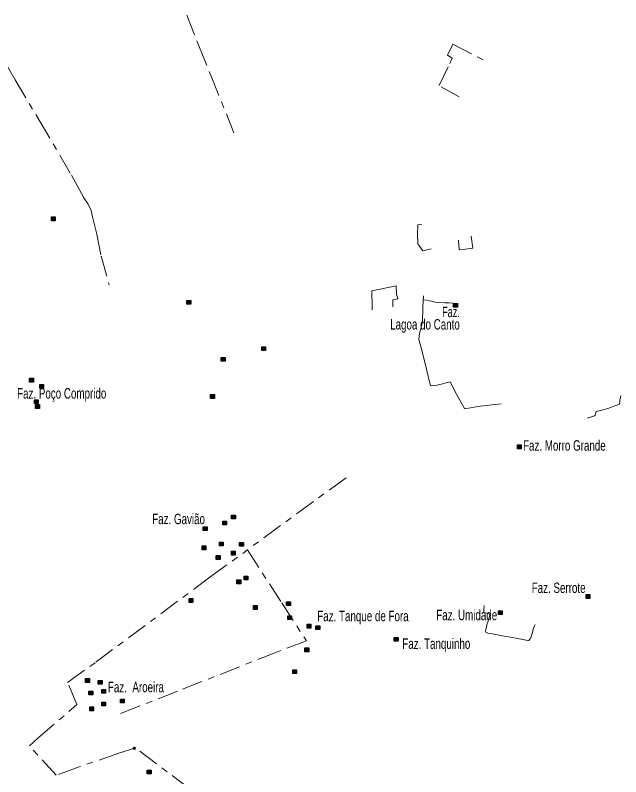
# Model space of a CAD drawing. Extents: x 445.4 to 500, y 8728.7 to 8784.
# Drawn here: x 450.41 to 459.68, y 8772.32 to 8783.97 of the extents above; entities that cross this region are included whole.
import ezdxf
from ezdxf.enums import TextEntityAlignment as Align

# ---------------------------------------------------------------- set-up
doc = ezdxf.new("R2010")
doc.units = 0
doc.header["$LTSCALE"] = 0.064
doc.header["$PDMODE"] = 32
doc.header["$PDSIZE"] = 0.032
doc.linetypes.add('DOT_DASHED', pattern=[7.7, 5, -1.2, 0.3, -1.2])
doc.layers.add('2', color=7, linetype='Continuous', lineweight=25)
doc.layers.add('22', color=7, linetype='DOT_DASHED', lineweight=13)
doc.layers.add('61', color=7, linetype='Continuous')

msp = doc.modelspace()

# ---------------------------------------------------------------- hatches: boundary and pattern name
at = {"layer": '2'}
for points in [[(450.9666, 8780.8868), (451.0246, 8780.8868), (451.0246, 8780.8288), (450.9666, 8780.8288)], [(453.0401, 8779.6071), (453.0981, 8779.6071), (453.0981, 8779.5491), (453.0401, 8779.5491)], [(457.1206, 8779.562), (457.1786, 8779.562), (457.1786, 8779.504), (457.1206, 8779.504)], [(454.1849, 8778.9008), (454.2429, 8778.9008), (454.2429, 8778.8428), (454.1849, 8778.8428)], [(453.565, 8778.7378), (453.623, 8778.7378), (453.623, 8778.6798), (453.565, 8778.6798)], [(450.6312, 8778.4171), (450.6892, 8778.4171), (450.6892, 8778.3591), (450.6312, 8778.3591)], [(450.7885, 8778.3217), (450.8465, 8778.3217), (450.8465, 8778.2637), (450.7885, 8778.2637)], [(450.7066, 8778.0871), (450.7646, 8778.0871), (450.7646, 8778.0291), (450.7066, 8778.0291)], [(453.4021, 8778.1673), (453.4601, 8778.1673), (453.4601, 8778.1093), (453.4021, 8778.1093)], [(450.7223, 8778.0151), (450.7803, 8778.0151), (450.7803, 8777.9571), (450.7223, 8777.9571)], [(458.0989, 8777.398), (458.1569, 8777.398), (458.1569, 8777.34), (458.0989, 8777.34)], [(453.7233, 8776.3229), (453.7813, 8776.3229), (453.7813, 8776.2649), (453.7233, 8776.2649)], [(453.5876, 8776.2324), (453.6456, 8776.2324), (453.6456, 8776.1744), (453.5876, 8776.1744)], [(453.289, 8776.1464), (453.347, 8776.1464), (453.347, 8776.0884), (453.289, 8776.0884)], [(453.2709, 8775.8521), (453.3289, 8775.8521), (453.3289, 8775.7941), (453.2709, 8775.7941)], [(453.5378, 8775.9109), (453.5958, 8775.9109), (453.5958, 8775.8529), (453.5378, 8775.8529)], [(453.8455, 8775.9064), (453.9035, 8775.9064), (453.9035, 8775.8484), (453.8455, 8775.8484)], [(453.7188, 8775.7706), (453.7768, 8775.7706), (453.7768, 8775.7126), (453.7188, 8775.7126)], [(453.4881, 8775.7027), (453.5461, 8775.7027), (453.5461, 8775.6447), (453.4881, 8775.6447)], [(453.9134, 8775.3903), (453.9714, 8775.3903), (453.9714, 8775.3323), (453.9134, 8775.3323)], [(453.8048, 8775.3314), (453.8628, 8775.3314), (453.8628, 8775.2734), (453.8048, 8775.2734)], [(453.0718, 8775.0462), (453.1298, 8775.0462), (453.1298, 8774.9882), (453.0718, 8774.9882)], [(459.1485, 8775.1073), (459.2065, 8775.1073), (459.2065, 8775.0493), (459.1485, 8775.0493)], [(454.058, 8774.9387), (454.116, 8774.9387), (454.116, 8774.8807), (454.058, 8774.8807)], [(454.5649, 8774.9964), (454.6229, 8774.9964), (454.6229, 8774.9384), (454.5649, 8774.9384)], [(457.8068, 8774.8599), (457.8648, 8774.8599), (457.8648, 8774.8019), (457.8068, 8774.8019)], [(454.5823, 8774.7825), (454.6403, 8774.7825), (454.6403, 8774.7245), (454.5823, 8774.7245)], [(454.8772, 8774.6523), (454.9352, 8774.6523), (454.9352, 8774.5943), (454.8772, 8774.5943)], [(455.0129, 8774.6297), (455.0709, 8774.6297), (455.0709, 8774.5717), (455.0129, 8774.5717)], [(456.212, 8774.4507), (456.27, 8774.4507), (456.27, 8774.3927), (456.212, 8774.3927)], [(454.8455, 8774.2901), (454.9035, 8774.2901), (454.9035, 8774.2321), (454.8455, 8774.2321)], [(454.66, 8773.9551), (454.718, 8773.9551), (454.718, 8773.8971), (454.66, 8773.8971)], [(451.4884, 8773.8216), (451.5464, 8773.8216), (451.5464, 8773.7636), (451.4884, 8773.7636)], [(451.6831, 8773.7926), (451.7411, 8773.7926), (451.7411, 8773.7346), (451.6831, 8773.7346)], [(451.7369, 8773.6558), (451.7949, 8773.6558), (451.7949, 8773.5978), (451.7369, 8773.5978)], [(451.5395, 8773.6303), (451.5975, 8773.6303), (451.5975, 8773.5723), (451.5395, 8773.5723)], [(451.7369, 8773.4611), (451.7949, 8773.4611), (451.7949, 8773.4031), (451.7369, 8773.4031)], [(452.0226, 8773.5066), (452.0806, 8773.5066), (452.0806, 8773.4486), (452.0226, 8773.4486)], [(451.5516, 8773.3882), (451.6096, 8773.3882), (451.6096, 8773.3302), (451.5516, 8773.3302)], [(452.4326, 8772.421), (452.4906, 8772.421), (452.4906, 8772.363), (452.4326, 8772.363)]]:
    msp.add_hatch(color=256, dxfattribs=at).paths.add_polyline_path(points)

# ---------------------------------------------------------------- linework, layer by layer
for points in [[(450.9666, 8780.8868), (451.0246, 8780.8868), (451.0246, 8780.8288), (450.9666, 8780.8288)], [(453.0401, 8779.6071), (453.0981, 8779.6071), (453.0981, 8779.5491), (453.0401, 8779.5491)], [(457.1206, 8779.562), (457.1786, 8779.562), (457.1786, 8779.504), (457.1206, 8779.504)], [(454.1849, 8778.9008), (454.2429, 8778.9008), (454.2429, 8778.8428), (454.1849, 8778.8428)], [(453.565, 8778.7378), (453.623, 8778.7378), (453.623, 8778.6798), (453.565, 8778.6798)], [(450.6312, 8778.4171), (450.6892, 8778.4171), (450.6892, 8778.3591), (450.6312, 8778.3591)], [(450.7885, 8778.3217), (450.8465, 8778.3217), (450.8465, 8778.2637), (450.7885, 8778.2637)], [(450.7066, 8778.0871), (450.7646, 8778.0871), (450.7646, 8778.0291), (450.7066, 8778.0291)], [(453.4021, 8778.1673), (453.4601, 8778.1673), (453.4601, 8778.1093), (453.4021, 8778.1093)], [(450.7223, 8778.0151), (450.7803, 8778.0151), (450.7803, 8777.9571), (450.7223, 8777.9571)], [(458.0989, 8777.398), (458.1569, 8777.398), (458.1569, 8777.34), (458.0989, 8777.34)], [(453.7233, 8776.3229), (453.7813, 8776.3229), (453.7813, 8776.2649), (453.7233, 8776.2649)], [(453.5876, 8776.2324), (453.6456, 8776.2324), (453.6456, 8776.1744), (453.5876, 8776.1744)], [(453.289, 8776.1464), (453.347, 8776.1464), (453.347, 8776.0884), (453.289, 8776.0884)], [(453.2709, 8775.8521), (453.3289, 8775.8521), (453.3289, 8775.7941), (453.2709, 8775.7941)], [(453.5378, 8775.9109), (453.5958, 8775.9109), (453.5958, 8775.8529), (453.5378, 8775.8529)], [(453.8455, 8775.9064), (453.9035, 8775.9064), (453.9035, 8775.8484), (453.8455, 8775.8484)], [(453.7188, 8775.7706), (453.7768, 8775.7706), (453.7768, 8775.7126), (453.7188, 8775.7126)], [(453.4881, 8775.7027), (453.5461, 8775.7027), (453.5461, 8775.6447), (453.4881, 8775.6447)], [(453.9134, 8775.3903), (453.9714, 8775.3903), (453.9714, 8775.3323), (453.9134, 8775.3323)], [(453.8048, 8775.3314), (453.8628, 8775.3314), (453.8628, 8775.2734), (453.8048, 8775.2734)], [(453.0718, 8775.0462), (453.1298, 8775.0462), (453.1298, 8774.9882), (453.0718, 8774.9882)], [(459.1485, 8775.1073), (459.2065, 8775.1073), (459.2065, 8775.0493), (459.1485, 8775.0493)], [(454.058, 8774.9387), (454.116, 8774.9387), (454.116, 8774.8807), (454.058, 8774.8807)], [(454.5649, 8774.9964), (454.6229, 8774.9964), (454.6229, 8774.9384), (454.5649, 8774.9384)], [(457.8068, 8774.8599), (457.8648, 8774.8599), (457.8648, 8774.8019), (457.8068, 8774.8019)], [(454.5823, 8774.7825), (454.6403, 8774.7825), (454.6403, 8774.7245), (454.5823, 8774.7245)], [(454.8772, 8774.6523), (454.9352, 8774.6523), (454.9352, 8774.5943), (454.8772, 8774.5943)], [(455.0129, 8774.6297), (455.0709, 8774.6297), (455.0709, 8774.5717), (455.0129, 8774.5717)], [(456.212, 8774.4507), (456.27, 8774.4507), (456.27, 8774.3927), (456.212, 8774.3927)], [(454.8455, 8774.2901), (454.9035, 8774.2901), (454.9035, 8774.2321), (454.8455, 8774.2321)], [(454.66, 8773.9551), (454.718, 8773.9551), (454.718, 8773.8971), (454.66, 8773.8971)], [(451.4884, 8773.8216), (451.5464, 8773.8216), (451.5464, 8773.7636), (451.4884, 8773.7636)], [(451.6831, 8773.7926), (451.7411, 8773.7926), (451.7411, 8773.7346), (451.6831, 8773.7346)], [(451.7369, 8773.6558), (451.7949, 8773.6558), (451.7949, 8773.5978), (451.7369, 8773.5978)], [(451.5395, 8773.6303), (451.5975, 8773.6303), (451.5975, 8773.5723), (451.5395, 8773.5723)], [(451.7369, 8773.4611), (451.7949, 8773.4611), (451.7949, 8773.4031), (451.7369, 8773.4031)], [(452.0226, 8773.5066), (452.0806, 8773.5066), (452.0806, 8773.4486), (452.0226, 8773.4486)], [(451.5516, 8773.3882), (451.6096, 8773.3882), (451.6096, 8773.3302), (451.5516, 8773.3302)], [(452.4326, 8772.421), (452.4906, 8772.421), (452.4906, 8772.363), (452.4326, 8772.363)]]:
    msp.add_lwpolyline(points, close=True, dxfattribs=at)
at = {"layer": '22'}
msp.add_line((455.4741, 8776.8956), (453.9654, 8775.7917), dxfattribs=at)
for points in [[(453.0369, 8783.9731), (453.2236, 8783.5026), (453.4093, 8783.0389), (453.6651, 8782.4105), (453.7586, 8782.1747)], [(449.9408, 8783.7821), (450.4111, 8782.9851), (450.7787, 8782.3666), (451.2709, 8781.5258), (451.3908, 8781.3119), (451.4627, 8781.1763), (451.5266, 8781.0805), (451.5745, 8780.9848), (451.5985, 8780.8691), (451.6584, 8780.6217), (451.7263, 8780.2865), (451.849, 8779.8399)], [(457.2078, 8782.7233), (456.898, 8782.8968), (457.0622, 8783.2354), (457.0979, 8783.3173), (457.0265, 8783.3637), (457.1091, 8783.5286), (457.5981, 8783.2783)], [(456.7768, 8780.4003), (456.6516, 8780.37), (456.5728, 8780.4723), (456.5688, 8780.6238), (456.5708, 8780.7655), (456.6324, 8780.7749)], [(457.1939, 8780.531), (457.2063, 8780.3837), (457.3044, 8780.391), (457.374, 8780.4024), (457.4138, 8780.4109), (457.3869, 8780.5915)], [(456.1894, 8779.5109), (456.1918, 8779.6157), (456.2668, 8779.6339), (456.2486, 8779.7028), (456.2405, 8779.8303), (455.9971, 8779.7817), (455.8674, 8779.7534), (455.8757, 8779.502), (455.8752, 8779.4667)], [(456.6594, 8779.6781), (456.652, 8779.5077), (456.642, 8779.2866), (456.6246, 8779.1922), (456.5997, 8779.1027), (456.5898, 8779.0108), (456.6321, 8778.8469), (456.6995, 8778.5792), (456.7691, 8778.3035), (456.8711, 8778.3134), (457.0701, 8778.3606), (457.1721, 8778.1619), (457.2805, 8777.9638), (457.288, 8777.9514), (457.5292, 8777.9886), (457.9376, 8778.0348)], [(457.1895, 8779.5637), (457.1159, 8779.5681), (457.0498, 8779.5696), (456.9858, 8779.5711), (456.9041, 8779.5771), (456.8394, 8779.5845), (456.7829, 8779.5957), (456.7487, 8779.6031), (456.7108, 8779.6113), (456.6587, 8779.6165)], [(459.1658, 8777.8077), (459.2458, 8777.8322), (459.2779, 8777.8416), (459.2854, 8777.8529), (459.2948, 8777.8935), (459.3033, 8777.9067), (459.3664, 8777.9227), (459.4097, 8777.9359), (459.4804, 8777.9547), (459.5359, 8777.9736), (459.5887, 8777.9952), (459.6518, 8778.015), (459.6612, 8778.0235), (459.665, 8778.0631), (459.6668, 8778.0866), (459.6725, 8778.1196), (459.6789, 8778.1533)], [(452.2554, 8772.7619), (451.9969, 8772.6799), (451.3733, 8772.4641), (451.0395, 8772.3415), (450.6274, 8772.7909), (450.7648, 8772.9135), (451.354, 8773.4235), (451.2116, 8773.7618), (451.6455, 8774.0733), (453.3921, 8775.3722), (453.9654, 8775.7917)], [(453.9654, 8775.7917), (454.49, 8774.9784), (454.8689, 8774.3988), (454.4229, 8774.2312), (452.8968, 8773.6293), (452.0178, 8773.2831)], [(457.5867, 8774.9406), (457.583, 8774.8813), (457.5818, 8774.8442), (457.589, 8774.8346), (457.6643, 8774.8107), (457.675, 8774.7892), (457.6595, 8774.739), (457.6464, 8774.6864), (457.6308, 8774.6433), (457.6225, 8774.611), (457.6129, 8774.5764), (457.6069, 8774.5524), (457.6129, 8774.5297), (457.6452, 8774.519), (457.7396, 8774.5022), (457.8412, 8774.4819), (457.926, 8774.4675), (457.9917, 8774.4556), (458.0981, 8774.4365), (458.1818, 8774.4197), (458.2296, 8774.4078), (458.2499, 8774.4006), (458.2726, 8774.4066), (458.3013, 8774.4472), (458.312, 8774.4807), (458.3335, 8774.5465), (458.3407, 8774.5823), (458.3574, 8774.6278), (458.3673, 8774.6512)], [(451.7456, 8769.4642), (452.0617, 8770.0681), (452.3997, 8770.6483), (452.7166, 8770.9859), (453.192, 8771.4501), (453.5617, 8771.7666), (452.2554, 8772.7619)]]:
    msp.add_lwpolyline(points, dxfattribs=at)
msp.add_point((452.2328, 8772.7547), dxfattribs=at)

# ---------------------------------------------------------------- texts
at = {"layer": '61'}
for s, width, p in [('Faz.', 0.65, (457.2155, 8779.353)), ('Lagoa do Canto', 0.7, (457.2155, 8779.163)), ('Faz. Gavião', 0.7, (453.3152, 8776.185)), ('Faz. Serrote', 0.7, (459.1398, 8775.1314))]:
    msp.add_text(s, height=0.16, dxfattribs=dict(at, width=width)).set_placement(p, align=Align.RIGHT)
at = {"layer": '61', "width": 0.7}
for s, p in [('Faz. Poço Comprido', (450.4402, 8778.1067)), ('Faz. Morro Grande', (458.1832, 8777.3088)), ('Faz. Tanque de Fora', (455.0339, 8774.6994)), ('Faz. Umidade', (456.8554, 8774.7148)), ('Faz. Tanquinho', (456.3356, 8774.2764)), ('Faz.  Aroeira', (451.8298, 8773.6126))]:
    msp.add_text(s, height=0.16, dxfattribs=at).set_placement(p)

doc.saveas('drawing.dxf')
